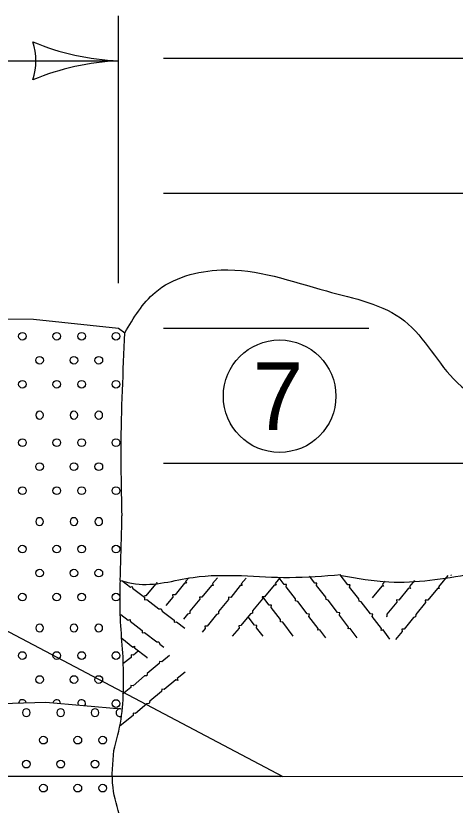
# Model space of a CAD drawing. Extents: x 49991.4 to 50021, y 49987.6 to 50011.4.
# Drawn here: x 50004.224 to 50004.614, y 49993.056 to 49993.758 of the extents above; entities that cross this region are included whole.
import ezdxf

# ---------------------------------------------------------------- set-up
doc = ezdxf.new("R2010")
doc.units = 0
for name, color, linetype in [('Level 1', 7, 'Continuous'), ('Level 2', 7, 'Continuous'), ('Level 3', 7, 'Continuous')]:
    doc.layers.add(name, color=color, linetype=linetype)

msp = doc.modelspace()

# ---------------------------------------------------------------- linework, layer by layer
at = {"layer": 'Level 1'}
for p, q in [((50004.35499, 49993.72055), (50005.57684, 49993.72055)), ((50004.35499, 49993.60055), (50005.57684, 49993.60055)), ((50004.35499, 49993.48055), (50004.53734, 49993.48055)), ((50004.35499, 49993.36055), (50004.67383, 49993.36055)), ((50004.31805, 49993.314), (50004.31805, 49993.31439)), ((50004.31648, 49993.2563), (50004.31652, 49993.25691)), ((50004.31652, 49993.25691), (50004.31652, 49993.2572))]:
    msp.add_line(p, q, dxfattribs=at)
for points in [[(50004.17861, 49993.48883), (50004.23958, 49993.4884), (50004.31501, 49993.48051), (50004.32066, 49993.47642)], [(50004.5561, 49993.20397), (50004.55, 49993.21227), (50004.5483, 49993.21187), (50004.5487, 49993.21347), (50004.5404, 49993.22417), (50004.541, 49993.22617), (50004.5389, 49993.22647), (50004.5306, 49993.23737), (50004.5287, 49993.23787), (50004.5285, 49993.23987), (50004.5202, 49993.25037), (50004.5206, 49993.25247), (50004.5185, 49993.25247), (50004.5119, 49993.26137)], [(50004.60748, 49993.26051), (50004.59908, 49993.25061), (50004.59978, 49993.24901), (50004.59818, 49993.24911), (50004.58968, 49993.23861), (50004.58748, 49993.23861), (50004.58778, 49993.23661), (50004.57898, 49993.22601), (50004.57888, 49993.22401), (50004.57698, 49993.22341), (50004.56858, 49993.21301), (50004.56658, 49993.21281), (50004.56698, 49993.21081), (50004.56088, 49993.20371)], [(50004.31801, 49993.25629), (50004.32561, 49993.25019), (50004.32721, 49993.25099), (50004.32731, 49993.24939), (50004.33801, 49993.24129), (50004.33801, 49993.23909), (50004.34001, 49993.23939), (50004.35091, 49993.23099), (50004.35291, 49993.23099), (50004.35361, 49993.22909), (50004.36441, 49993.22109), (50004.36451, 49993.21909), (50004.36651, 49993.21949), (50004.37391, 49993.21369)], [(50004.3487, 49993.25477), (50004.3486, 49993.25467), (50004.3494, 49993.25307), (50004.3478, 49993.25307), (50004.3392, 49993.24267), (50004.3381, 49993.24267)], [(50004.3774, 49993.25867), (50004.3745, 49993.25537), (50004.3753, 49993.25377), (50004.3737, 49993.25377), (50004.3652, 49993.24337), (50004.363, 49993.24337), (50004.3633, 49993.24137), (50004.35693, 49993.23385)], [(50004.4029, 49993.25867), (50004.3984, 49993.25347), (50004.3991, 49993.25187), (50004.3975, 49993.25187), (50004.389, 49993.24147), (50004.3868, 49993.24147), (50004.3871, 49993.23947), (50004.3783, 49993.22887), (50004.3782, 49993.22687), (50004.3763, 49993.22617), (50004.37278, 49993.22176)], [(50004.4284, 49993.25837), (50004.424, 49993.25327), (50004.4247, 49993.25167), (50004.4231, 49993.25167), (50004.4146, 49993.24117), (50004.4125, 49993.24127), (50004.4127, 49993.23927), (50004.4039, 49993.22867), (50004.4038, 49993.22667), (50004.402, 49993.22597), (50004.3936, 49993.21557), (50004.3916, 49993.21547), (50004.3919, 49993.21347), (50004.38919, 49993.21022)], [(50004.4583, 49993.25857), (50004.4541, 49993.25367), (50004.4549, 49993.25207), (50004.4533, 49993.25217), (50004.4447, 49993.24167), (50004.4426, 49993.24177), (50004.4428, 49993.23977), (50004.434, 49993.22917), (50004.434, 49993.22717), (50004.4321, 49993.22647), (50004.4237, 49993.21607), (50004.4217, 49993.21597), (50004.422, 49993.21397), (50004.416, 49993.20677)], [(50004.499, 49993.20517), (50004.4937, 49993.21247), (50004.4919, 49993.21207), (50004.4924, 49993.21357), (50004.4841, 49993.22427), (50004.4846, 49993.22637), (50004.4826, 49993.22657), (50004.4743, 49993.23757), (50004.4723, 49993.23807), (50004.4721, 49993.23997), (50004.4639, 49993.25057), (50004.4642, 49993.25257), (50004.4622, 49993.25267), (50004.4578, 49993.25847)], [(50004.5268, 49993.20537), (50004.5207, 49993.21367), (50004.5189, 49993.21327), (50004.5193, 49993.21487), (50004.5111, 49993.22547), (50004.5116, 49993.22757), (50004.5096, 49993.22787), (50004.5013, 49993.23877), (50004.4993, 49993.23927), (50004.4991, 49993.24127), (50004.4909, 49993.25177), (50004.4912, 49993.25377), (50004.4892, 49993.25387), (50004.4846, 49993.25997)], [(50004.55188, 49993.25551), (50004.54958, 49993.25281), (50004.55038, 49993.25121), (50004.54878, 49993.25121), (50004.54028, 49993.24071)], [(50004.57798, 49993.25621), (50004.57338, 49993.25091), (50004.57418, 49993.24921), (50004.57258, 49993.24931), (50004.56408, 49993.23881), (50004.56188, 49993.23891), (50004.56208, 49993.23681), (50004.55328, 49993.22631), (50004.55328, 49993.22421), (50004.55275, 49993.22405)], [(50004.4702, 49993.20667), (50004.4608, 49993.21907), (50004.4589, 49993.21957), (50004.4587, 49993.22157), (50004.4504, 49993.23217), (50004.4508, 49993.23417), (50004.4487, 49993.23427), (50004.4432, 49993.24167)], [(50004.317, 49993.22611), (50004.3236, 49993.22081), (50004.3252, 49993.22161), (50004.3252, 49993.22001), (50004.336, 49993.21181), (50004.336, 49993.20971), (50004.338, 49993.21001), (50004.3489, 49993.20161), (50004.3509, 49993.20161), (50004.3516, 49993.19971), (50004.35529, 49993.19697)], [(50004.4434, 49993.20677), (50004.4375, 49993.21427), (50004.4379, 49993.21627), (50004.4358, 49993.21637), (50004.4302, 49993.22397)], [(50004.31804, 49993.20488), (50004.32764, 49993.19708), (50004.32924, 49993.19798), (50004.32924, 49993.19638), (50004.34004, 49993.18818), (50004.34004, 49993.18708)], [(50004.33247, 49993.19331), (50004.32824, 49993.1897), (50004.32624, 49993.19), (50004.32624, 49993.1879), (50004.31884, 49993.1821)], [(50004.36022, 49993.18956), (50004.35344, 49993.1839), (50004.35134, 49993.1843), (50004.35114, 49993.1823), (50004.34054, 49993.1736), (50004.34004, 49993.1716), (50004.33814, 49993.1714), (50004.32784, 49993.1627), (50004.32584, 49993.163), (50004.32584, 49993.161), (50004.31854, 49993.1551)], [(50004.37404, 49993.1747), (50004.36704, 49993.1692), (50004.36754, 49993.1674), (50004.36594, 49993.1678), (50004.35554, 49993.1592), (50004.35344, 49993.1596), (50004.35324, 49993.1576), (50004.34264, 49993.1489), (50004.34214, 49993.1469), (50004.34024, 49993.1467), (50004.32994, 49993.138), (50004.32794, 49993.1383), (50004.32794, 49993.1362), (50004.31644, 49993.12707)], [(50004.19101, 49993.14623), (50004.25047, 49993.14814), (50004.31739, 49993.14216)]]:
    msp.add_lwpolyline(points, dxfattribs=at)
for centre in [(50004.2296, 49993.47333), (50004.26008, 49993.47333), (50004.28222, 49993.47333), (50004.3127, 49993.47333), (50004.24484, 49993.452), (50004.24484, 49993.452), (50004.27532, 49993.452), (50004.29746, 49993.452), (50004.2296, 49993.43066), (50004.26008, 49993.43066), (50004.28222, 49993.43066), (50004.3127, 49993.43066), (50004.2296, 49993.37873), (50004.26008, 49993.37873), (50004.28222, 49993.37873), (50004.3127, 49993.37873), (50004.24484, 49993.3574), (50004.24484, 49993.3574), (50004.27532, 49993.3574), (50004.29746, 49993.3574), (50004.2296, 49993.33606), (50004.26008, 49993.33606), (50004.28222, 49993.33606), (50004.3127, 49993.33606), (50004.2296, 49993.28413), (50004.26008, 49993.28413), (50004.28222, 49993.28413), (50004.3127, 49993.28413), (50004.24484, 49993.2628), (50004.24484, 49993.2628), (50004.27532, 49993.2628), (50004.29746, 49993.2628), (50004.2296, 49993.24146), (50004.26008, 49993.24146), (50004.28222, 49993.24146), (50004.3127, 49993.24146), (50004.2296, 49993.18953), (50004.26008, 49993.18953), (50004.28222, 49993.18953), (50004.3127, 49993.18953), (50004.24484, 49993.1682), (50004.24484, 49993.1682), (50004.27532, 49993.1682), (50004.29746, 49993.1682), (50004.3127, 49993.14686), (50004.2483, 49993.1143), (50004.27878, 49993.1143), (50004.30092, 49993.1143), (50004.23306, 49993.09296), (50004.26354, 49993.09296), (50004.26354, 49993.09296), (50004.29402, 49993.09296), (50004.2483, 49993.07162), (50004.27878, 49993.07162), (50004.30092, 49993.07162)]:
    msp.add_circle(centre, 0.00341, dxfattribs=at)
for centre, start, end in [((50004.24484, 49993.40323), 0, 180), ((50004.24484, 49993.40312), 180, 0), ((50004.24484, 49993.40312), 180, 0), ((50004.27532, 49993.40323), 0, 180), ((50004.27532, 49993.40312), 180, 0), ((50004.29746, 49993.40323), 0, 180), ((50004.29746, 49993.40312), 180, 0), ((50004.24484, 49993.30863), 0, 180), ((50004.27532, 49993.30863), 0, 180), ((50004.29746, 49993.30863), 0, 180), ((50004.24484, 49993.30852), 180, 0), ((50004.24484, 49993.30852), 180, 0), ((50004.27532, 49993.30852), 180, 0), ((50004.29746, 49993.30852), 180, 0), ((50004.60772, 49993.2628), 321.66168, 330.74328), ((50004.24484, 49993.21403), 0, 180), ((50004.24484, 49993.21392), 180, 0), ((50004.24484, 49993.21392), 180, 0), ((50004.27532, 49993.21403), 0, 180), ((50004.27532, 49993.21392), 180, 0), ((50004.29746, 49993.21403), 0, 180), ((50004.29746, 49993.21392), 180, 0), ((50004.2296, 49993.14686), 12.10537, 171.55963), ((50004.26008, 49993.14686), 1.90051, 167.89515), ((50004.28222, 49993.14686), 327.77703, 202.01864), ((50004.23306, 49993.13879), 0, 180), ((50004.26354, 49993.13879), 0, 180), ((50004.29402, 49993.13879), 0, 180), ((50004.31616, 49993.13879), 68.93843, 180), ((50004.23306, 49993.13868), 180, 0), ((50004.26354, 49993.13868), 180, 0), ((50004.26354, 49993.13868), 180, 0), ((50004.29402, 49993.13868), 180, 0), ((50004.31616, 49993.13868), 180, 286.80547)]:
    msp.add_arc(centre, 0.00341, start, end, dxfattribs=at)
for points in [[(50004.32066, 49993.47642), (50004.34743, 49993.51226), (50004.40617, 49993.53229), (50004.49962, 49993.5136), (50004.56904, 49993.4869), (50004.61577, 49993.43216), (50004.69053, 49993.3841), (50004.74927, 49993.32937), (50004.80935, 49993.30133), (50004.85741, 49993.27864)], [(50004.31805, 49993.31439), (50004.31733, 49993.37364), (50004.32066, 49993.47642)], [(50004.31805, 49993.31439), (50004.31733, 49993.37364), (50004.32066, 49993.47642)], [(50004.31652, 49993.2572), (50004.31803, 49993.31322), (50004.31805, 49993.314)], [(50004.31652, 49993.2572), (50004.31803, 49993.31322), (50004.31805, 49993.314)], [(50004.31648, 49993.2563), (50004.33, 49993.25327), (50004.3813, 49993.25897), (50004.4668, 49993.25897), (50004.5124, 49993.26147)], [(50004.51306, 49993.26077), (50004.55518, 49993.25491), (50004.6278, 49993.26206)], [(50004.31902, 49993.1884), (50004.31632, 49993.2437), (50004.31665, 49993.2563)], [(50004.31088, 49993.10495), (50004.31722, 49993.1329), (50004.31902, 49993.1884)], [(50004.28517, 49992.91069), (50004.29732, 49992.9109), (50004.31722, 49992.9194), (50004.31152, 49992.9705), (50004.32012, 49993.0188), (50004.31007, 49993.07217), (50004.31088, 49993.10495)]]:
    msp.add_spline(points, degree=3, dxfattribs=at)
at = {"layer": 'Level 2'}
msp.add_circle((50004.45807, 49993.42002), 0.05, dxfattribs=at)
at = {"layer": 'Level 3'}
for p, q in [((50004.31501, 49993.52051), (50004.31501, 49993.75818)), ((50003.83501, 49993.71818), (50004.31501, 49993.71818)), ((50003.98875, 49993.33099), (50004.4608, 49993.08212)), ((50004.45902, 49993.08212), (50004.08366, 49993.08212)), ((50004.45902, 49993.08212), (50005.49096, 49993.08293))]:
    msp.add_line(p, q, dxfattribs=at)
for centre, radius, start, end in [((50004.32416, 49993.94032), 0.22232, 247.45601, 267.63952), ((50004.18679, 49993.71818), 0.05477, 342.13882, 17.86118), ((50004.3265, 49993.48547), 0.233, 92.82731, 112.07716)]:
    msp.add_arc(centre, radius, start, end, dxfattribs=at)

# ---------------------------------------------------------------- texts
at = {"layer": 'Level 2'}
msp.add_text('7', height=0.06, dxfattribs=at).set_placement((50004.43427, 49993.39002))

doc.saveas('drawing.dxf')
